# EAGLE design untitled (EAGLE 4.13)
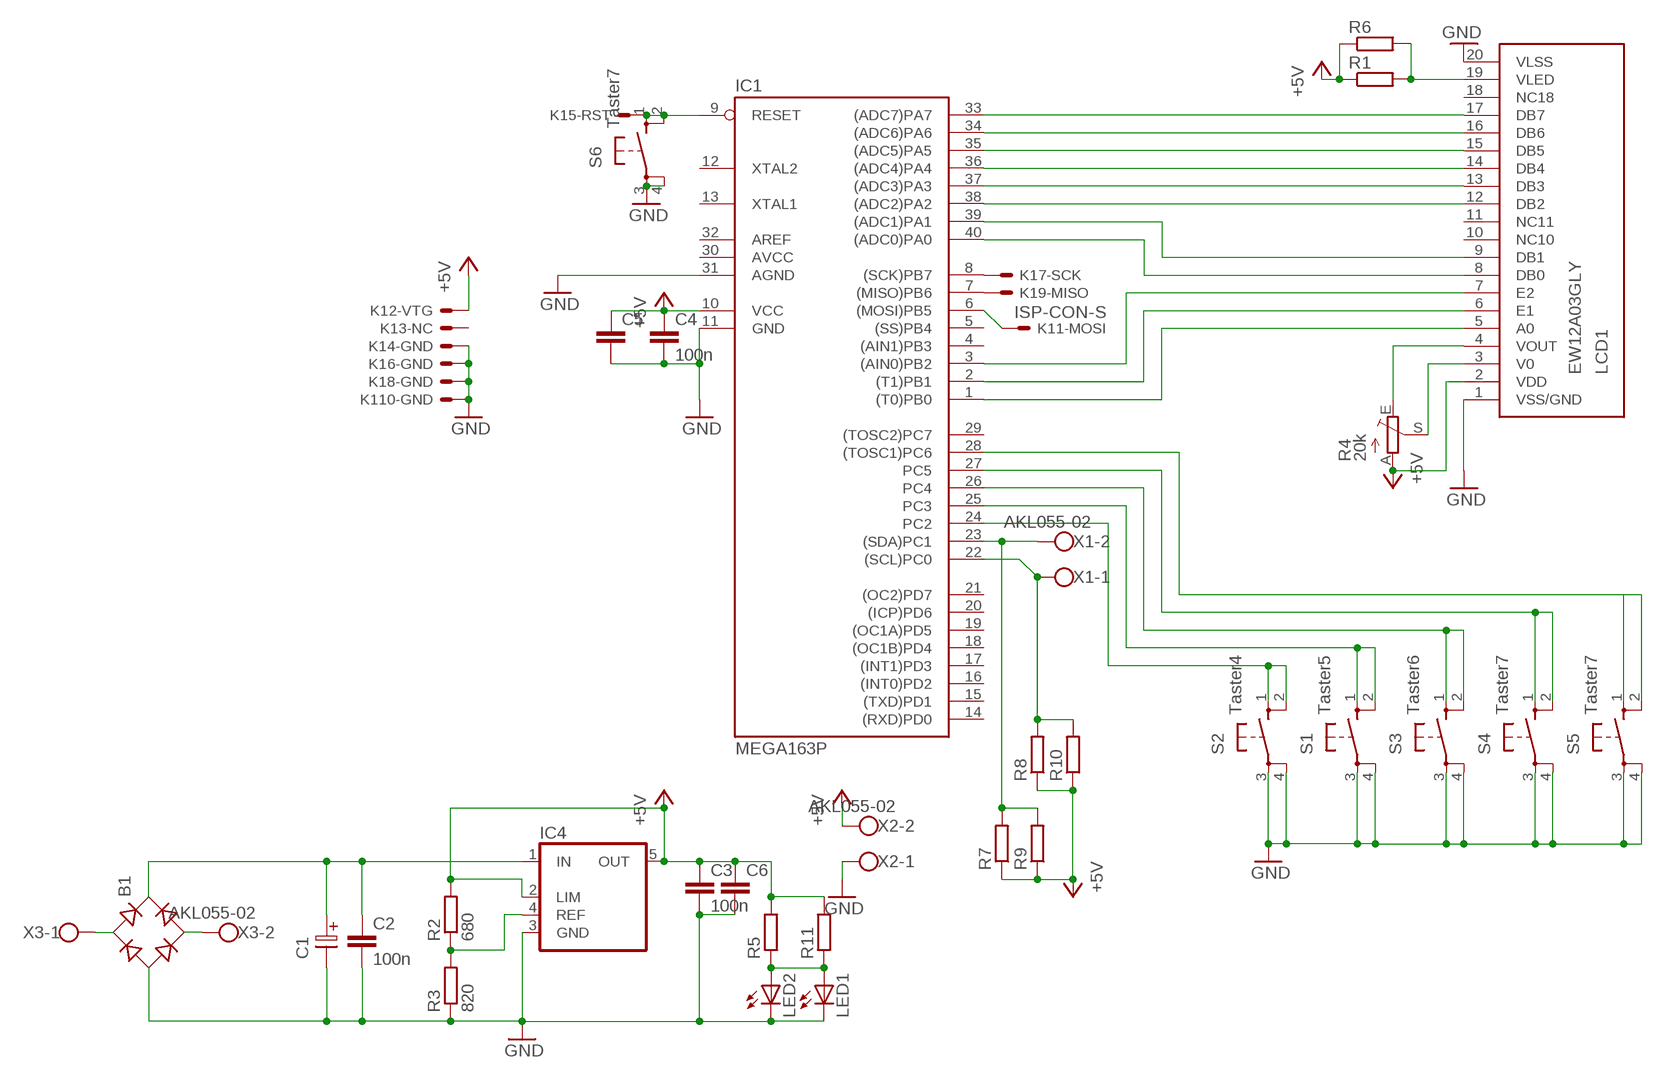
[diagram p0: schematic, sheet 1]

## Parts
B1  RB1A  [RB1A]
C1  _ELC5,0  [ES-5]
C2  100n  C-EU025-025X050  [C025-025X050]
C3  100n  C-EU025-025X050  [C025-025X050]
C4  100n  C-EU025-025X050  [C025-025X050]
C5  C-EUC0805  [C0805]
C6  C-EUC0805  [C0805]
IC1  MEGA163P  [DIL40]
IC4  L200  [L200S]
K1  ISP-CON-S  [ML10]
LCD1  EW12A03GLY  [12A03]
LED1  LED5MM  [LED5MM]
LED2  LEDP-LCC-2-BACK  [P-LCC-2-TOPLED-RG]
R1  R-EU_0204/7  [0204/7]
R2  680  R-EU_0204/2V  [0204V]
R3  820  R-EU_0204/2V  [0204V]
R4  20k  TRIM_EU-S63X  [S63X]
R5  R-EU_M0805  [M0805]
R6  R-EU_R0805  [R0805]
R7  R-EU_0204/7  [0204/7]
R8  R-EU_0204/7  [0204/7]
R9  R-EU_M0805  [M0805]
R10  R-EU_M0805  [M0805]
R11  R-EU_0204/2V  [0204V]
S1  Taster5  10XX  [B3F-10XX]
S2  Taster4  10XX  [B3F-10XX]
S3  Taster6  10XX  [B3F-10XX]
S4  Taster7  10XX  [B3F-10XX]
S5  Taster7  10XX  [B3F-10XX]
S6  Taster7  10XX  [B3F-10XX]
X1  AKL055-02  [AKL055-02]
X2  AKL055-02  [AKL055-02]
X3  AKL055-02  [AKL055-02]

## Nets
+5V: C3.1 C4.1 C5.1 C6.1 IC1.10(VCC) IC4.2(LIM) IC4.5(OUT) K1.2 LCD1.2(VDD) R1.1 R2.2 R4.A R5.2 R6.1 R7.1 R8.1 R9.1 R10.1 R11.2 X2.P$2
GND: B1.- C1.2 C2.2 C3.2 C4.2 C5.2 C6.2 IC1.11(GND) IC1.31(AGND) IC4.3(GND) K1.4 K1.6 K1.8 K1.10 LCD1.1(VSS/GND) LCD1.20(VLSS) LED1.K(C) LED2.C R3.1 S1.3 S1.4 S2.3 S2.4 S3.3 S3.4 S4.3 S4.4 S5.3 S5.4 S6.3 S6.4 X2.P$1
N$1: IC1.40((ADC0)PA0) LCD1.8(DB0)
N$2: IC1.39((ADC1)PA1) LCD1.9(DB1)
N$3: IC1.38((ADC2)PA2) LCD1.12(DB2)
N$4: IC1.37((ADC3)PA3) LCD1.13(DB3)
N$5: IC1.36((ADC4)PA4) LCD1.14(DB4)
N$6: IC1.35((ADC5)PA5) LCD1.15(DB5)
N$7: IC1.34((ADC6)PA6) LCD1.16(DB6)
N$8: IC1.33((ADC7)PA7) LCD1.17(DB7)
N$9: IC1.1((T0)PB0) LCD1.5(A0)
N$10: IC1.2((T1)PB1) LCD1.6(E1)
N$11: IC1.3((AIN0)PB2) LCD1.7(E2)
N$12: LCD1.4(VOUT) R4.E
N$13: LCD1.3(V0) R4.S
N$14: IC1.6((MOSI)PB5) K1.1
N$15: LCD1.19(VLED) R1.2 R6.2
N$16: IC1.9(RESET) K1.5 S6.1 S6.2
N$17: IC1.8((SCK)PB7) K1.7
N$18: IC1.7((MISO)PB6) K1.9
N$19: IC1.22((SCL)PC0) R8.2 R10.2 X1.P$1
N$20: IC1.23((SDA)PC1) R7.2 R9.2 X1.P$2
N$23: B1.AC2 X3.P$2
N$24: B1.AC1 X3.P$1
N$26: LED1.A LED2.A R5.1 R11.1
N$27: IC1.24(PC2) S2.1 S2.2
N$28: IC1.25(PC3) S1.1 S1.2
N$29: IC1.26(PC4) S3.1 S3.2
N$30: IC1.27(PC5) S4.1 S4.2
N$31: IC1.28((TOSC1)PC6) S5.1 S5.2
N$51: B1.+ C1.1 C2.1 IC4.1(IN)
N$54: IC4.4(REF) R2.1 R3.2
Unconnected: IC1.4((AIN1)PB3) IC1.5((SS)PB4) IC1.12(XTAL2) IC1.13(XTAL1) IC1.14((RXD)PD0) IC1.15((TXD)PD1) IC1.16((INT0)PD2) IC1.17((INT1)PD3) IC1.18((OC1B)PD4) IC1.19((OC1A)PD5) IC1.20((ICP)PD6) IC1.21((OC2)PD7) IC1.29((TOSC2)PC7) K1.3 LCD1.10(NC10) LCD1.11(NC11) LCD1.18(NC18)

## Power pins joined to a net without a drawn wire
AREF: IC1.32(AREF)
AVCC: IC1.30(AVCC)

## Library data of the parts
B1 = rectifier:RB1A: RECTIFIER 1 A
C1 = Verschiedenes:_ELC
C2-C6 = rcl:C-EU: CAPACITOR, European symbol
IC1 = atmel:MEGA163*P: MICROCONTROLLER 16 Kbytes FLASH, 1 Kbytes EEPROM 1 Kbytes SRAM UART 8-channel 10 bit ADC hardware multiplier
IC4 = v-reg:L200: VOLTAGE REGULATOR
K1 = I2C:ISP-CON-S
LCD1 = EMERGING:EW12A03GLY
LED1 LED2 = led:LED: LED
R1-R3 R5-R11 = rcl:R-EU_: RESISTOR, European symbol
R4 = pot:TRIM_EU-: POTENTIOMETER
S1-S6 = KEY_B:10XX
X1-X3 = con-riacon:AKL055-02: Anreihbare Anschlussklemme

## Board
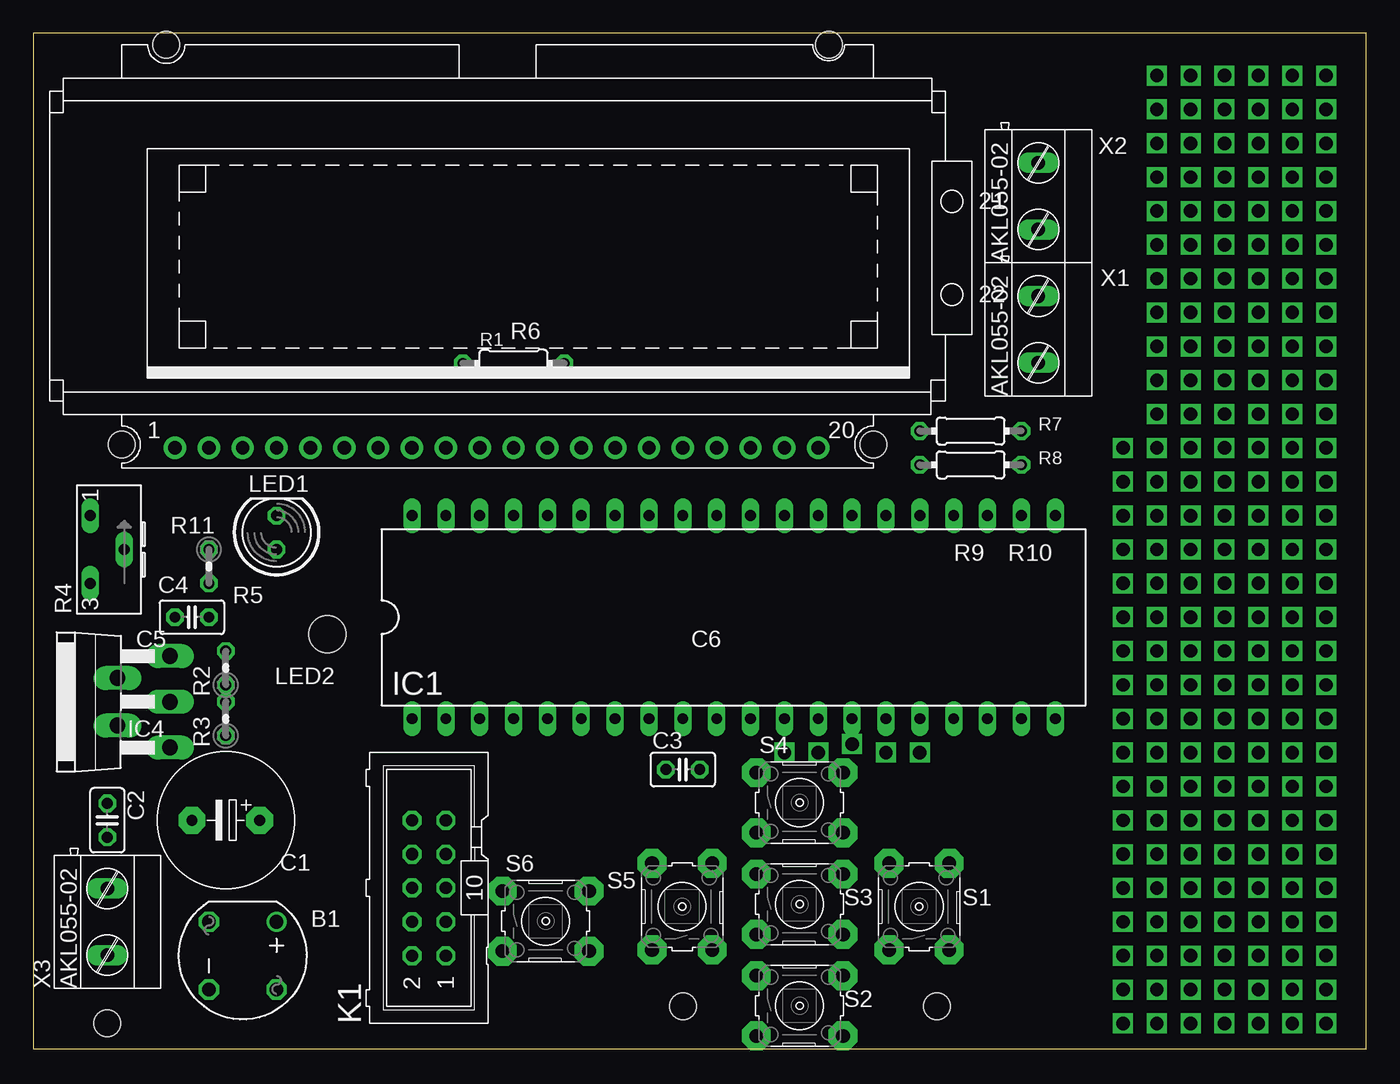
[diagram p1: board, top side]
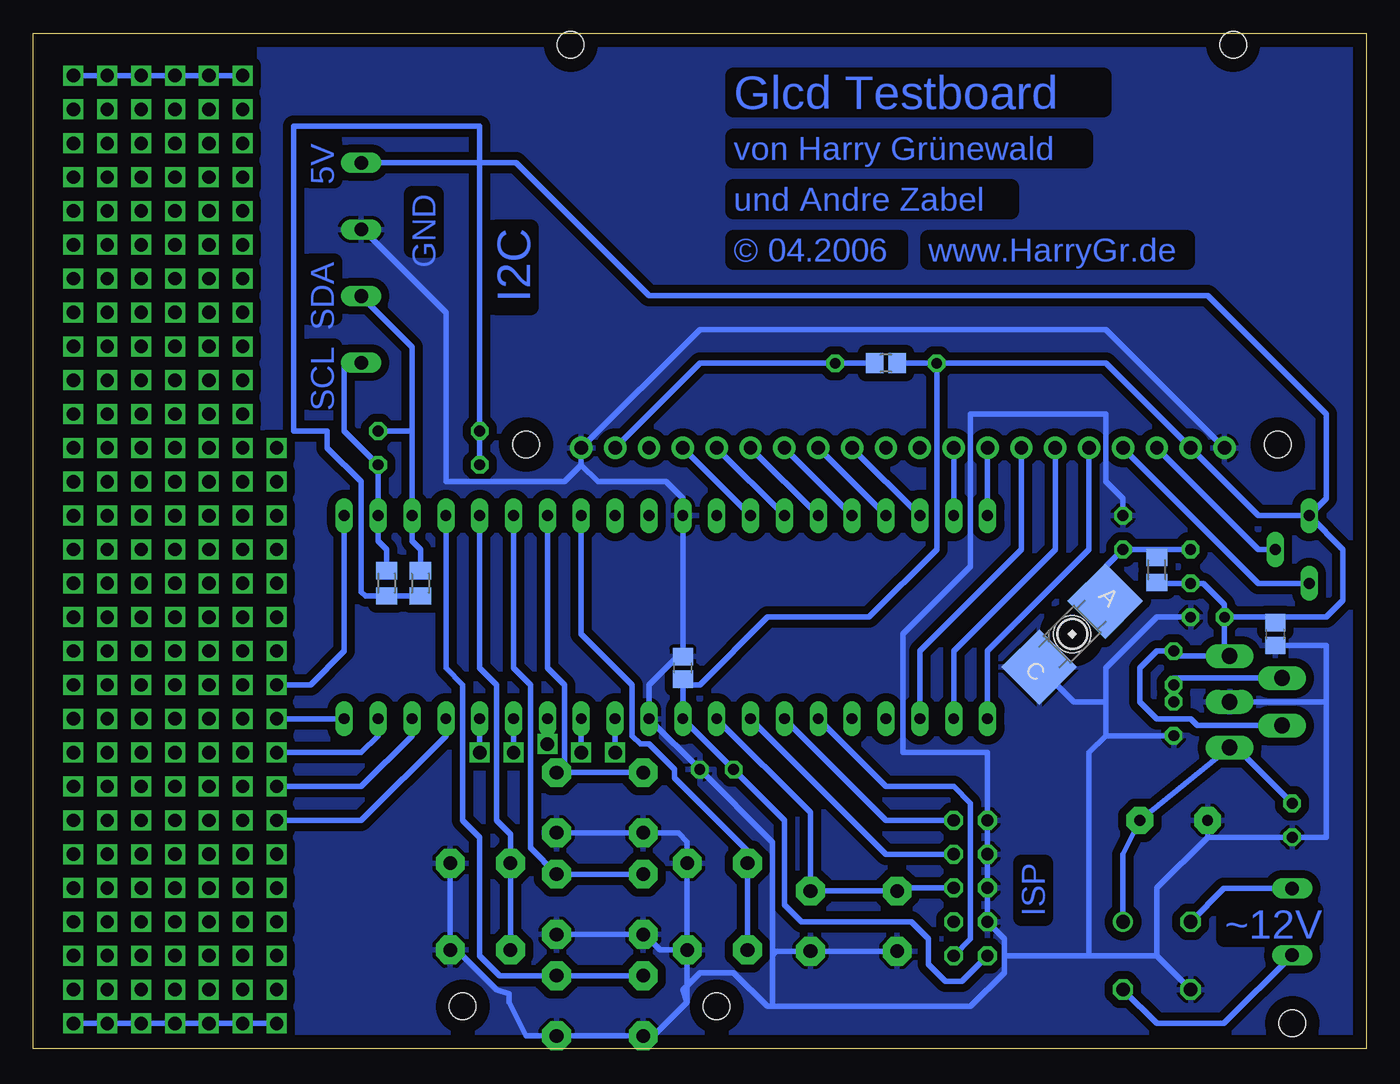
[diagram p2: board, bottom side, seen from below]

Size 100 x 76.19 mm. Coordinates in mm from the lower left corner, seen from the top.
Outline: 0,0 100,0 100,76.19 0,76.19 0,0
Copper layers (1*16): Top 0.035mm / dielectric 1.5mm / Bottom 0.035mm
Design rules "default": minimum track width 10mil, minimum drill 24mil, track to track 8mil, track to pad 8mil, pad to pad 8mil, via to via 8mil, smd to smd 8mil, copper to edge 40mil, drill to drill 8mil, minimum pad ring 10mil, minimum via ring 8mil, stop-mask expansion 4mil, vias tented up to drill 0mil, thermal gap 10mil
Holes 2 mm at 48.73,3.17 67.78,3.17 5.55,1.9

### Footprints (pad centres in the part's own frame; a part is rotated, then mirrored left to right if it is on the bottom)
RB1A = drill 1.016 round: + -2.54,2.54 | drill 1.016 octagon: - 2.54,-2.54; AC1 2.54,2.54; AC2 -2.54,-2.54
ES-5 = drill 0.813 pad 2.007 octagon: 1 -2.54,0; 2 2.54,0
C025-025X050 = drill 0.813 octagon: 1 -1.27,0; 2 1.27,0
C0805 = smd 1.3 x 1.5: 1 -0.85,0; 2 0.85,0
DIL40 = drill 0.813 long: 1 -24.13,-7.62; 2 -21.59,-7.62; 3 -19.05,-7.62; 4 -16.51,-7.62; 5 -13.97,-7.62; 6 -11.43,-7.62; 7 -8.89,-7.62; 8 -6.35,-7.62; 9 -3.81,-7.62; 10 -1.27,-7.62; 11 1.27,-7.62; 12 3.81,-7.62; 13 6.35,-7.62; 14 8.89,-7.62; 15 11.43,-7.62; 16 13.97,-7.62; 17 16.51,-7.62; 18 19.05,-7.62; 19 21.59,-7.62; 20 24.13,-7.62; 21 24.13,7.62; 22 21.59,7.62; 23 19.05,7.62; 24 16.51,7.62; 25 13.97,7.62; 26 11.43,7.62; 27 8.89,7.62; 28 6.35,7.62; 29 3.81,7.62; 30 1.27,7.62; 31 -1.27,7.62; 32 -3.81,7.62; 33 -6.35,7.62; 34 -8.89,7.62; 35 -11.43,7.62; 36 -13.97,7.62; 37 -16.51,7.62; 38 -19.05,7.62; 39 -21.59,7.62; 40 -24.13,7.62
L200S = drill 1.194 long: 1 -3.429,-8.509; 2 -1.778,-4.572; 3 0,-8.509; 4 1.778,-4.572; 5 3.429,-8.509
ML10 = drill 0.914 octagon: 1 -5.08,-1.27; 2 -5.08,1.27; 3 -2.54,-1.27; 4 -2.54,1.27; 5 0,-1.27; 6 0,1.27; 7 2.54,-1.27; 8 2.54,1.27; 9 5.08,-1.27; 10 5.08,1.27
12A03 = drill 1 pad 1.676 round: 1 0,0; 2 2.54,0; 3 5.08,0; 4 7.62,0; 5 10.16,0; 6 12.7,0; 7 15.24,0; 8 17.78,0; 9 20.32,0; 10 22.86,0; 11 25.4,0; 12 27.94,0; 13 30.48,0; 14 33.02,0; 15 35.56,0; 16 38.1,0; 17 40.64,0; 18 43.18,0; 19 45.72,0; 20 48.26,0 | hole 2: -4,0.25; 52.4,0.25; -0.65,30.25; 49.05,30.25
LED5MM = drill 0.813 octagon: A -1.27,0; K 1.27,0
P-LCC-2-TOPLED-RG = smd 4 x 4: A 0,3.5; C 0,-3.5 | hole 2.8: 0,0
0204/7 = drill 0.813 octagon: 1 -3.81,0; 2 3.81,0
0204V = drill 0.813 octagon: 1 -1.27,0; 2 1.27,0
S63X = drill 0.813 long: A 2.54,0; E -2.54,0; S 0,-2.54
M0805 = smd 1.3 x 1.6: 1 -0.95,0; 2 0.95,0
R0805 = smd 1.3 x 1.5: 1 -0.85,0; 2 0.85,0
B3F-10XX = drill 1.016 pad 2.159 octagon: 1 -3.379,2.312; 2 3.123,2.312; 3 -3.379,-2.209; 4 3.123,-2.209
AKL055-02 = drill 1.016 long: P$1 0,-2.5; P$2 0,2.5

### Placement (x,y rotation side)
B1  15.71,6.98 270 top
C1  14.44,17.14 180 top
C2  5.55,17.14 270 top
C3  48.73,20.95 0 top
C4  11.9,32.38 0 top
C5  6.82,31.11 270 bottom
C6  51.27,28.57 90 bottom
IC1  52.54,32.38 0 top
IC4  1.74,26.03 90 top
K1  29.68,12.06 90 top
LCD1  10.63,45.08 0 top
LED1  18.25,38.73 90 top
LED2  22.06,31.11 315 bottom
R1  36.03,51.43 0 top
R2  14.44,28.57 90 top
R3  14.44,24.76 90 top
R4  4.28,37.46 90 top
R5  15.71,35.94 270 bottom
R6  36.03,51.43 180 bottom
R7  70.32,46.35 0 top
R8  70.32,43.81 0 top
R9  70.95,34.92 90 bottom
R10  73.5,34.92 90 bottom
R11  13.17,36.19 270 top
S1  66.51,10.79 90 top
S2  57.62,3.17 0 top
S3  57.62,10.79 0 top
S4  57.62,18.41 0 top
S5  48.73,10.79 90 top
S6  38.57,9.52 0 top
X1  75.4,53.97 0 top
X2  75.4,63.97 0 top
X3  5.55,9.52 0 top

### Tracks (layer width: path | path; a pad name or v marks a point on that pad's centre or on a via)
+5V
  Bottom 0.406: R1.1 19.52,51.43 LCD1.2 8.09,40 R4.A | K1.2 30.31,5.08 31.58,5.08 32.85,6.35 32.85,8.25 34.12,9.52 42.38,9.52 43.65,10.79 43.65,17.14 C3.1 IC1.10 51.27,27.3 | R1.1 32.22,37.46 37.3,32.38 44.92,32.38 50,27.3 51.27,27.3 | R4.A 3.01,41.27 3.01,47.62 11.9,56.51 53.81,56.51 63.77,66.47 66.51,66.47 | C4.1 10.63,29.46 IC4.5 14.44,29.46 R2.2 15.71,29.84 16.98,28.57 16.98,26.03 15.71,24.76 13.17,24.76 12.66,24.25 IC4.2 | C4.1 3.01,32.38 | 3.01,32.38 1.74,33.65 1.74,37.46 R4.A | C4.1 10.63,33.33 12.22,34.92 R11.2 15.71,34.92 R5.2 | R1.1 R6.1 | 3.01,32.38 6.82,32.38 C5.1 | 66.51,66.47 X2.P$2 | 51.27,27.3 C6.1 | R8.1 R7.1 66.51,66.47 | 66.51,66.47 66.51,69.21 80.48,69.21 80.48,46.35 77.94,46.35 77.94,45.08 75.4,42.54 75.4,34.29 75.08,33.97 | 75.08,33.97 R10.1 | R10.1 R9.1 | R10.1 73.5,34.29 73.81,33.97 75.08,33.97
GND
  Bottom 0.406: LCD1.1 19.52,53.97 50,53.97 LCD1.20 | 27.14,6.98 27.14,5.71 29.68,3.17 44.54,3.17 | 27.14,6.98 27.14,8.25 K1.4 K1.6 K1.8 K1.10 28.41,22.22 34.76,22.22 34.76,31.11 29.68,36.19 29.68,47.62 19.52,47.62 19.52,42.54 18.25,41.27 LED1.K | B1.- 15.71,6.98 | 15.71,6.98 15.71,12.06 11.9,15.87 | 11.9,15.87 C1.2 | 11.9,15.87 C2.2 3.01,15.87 3.01,26.03 | 3.01,26.03 IC4.3 | 19.52,23.49 20.79,22.22 20.79,6.98 | 19.52,23.49 R3.1 | 15.71,6.98 20.79,6.98 | C4.2 15.71,32.38 19.52,28.57 19.52,26.03 | 19.52,23.49 19.52,26.03 | 58.89,43.81 57.62,42.54 52.54,42.54 51.27,41.27 IC1.31 51.27,29.84 53.81,27.3 IC1.11 C3.2 44.54,15.49 44.54,6.98 | 20.79,6.98 27.14,6.98 | S4.4 S4.3 54.14,16.2 | S3.4 S3.3 54.14,8.58 52.97,7.41 S5.3 | S5.3 S5.4 50.94,14.27 | 54.14,16.2 51.6,16.2 50.94,15.54 50.94,14.27 | 54.14,16.2 53.81,15.87 | 50.94,14.27 51.27,14.6 | 60.16,0.63 59.83,0.96 S2.3 53.48,0.96 50.94,3.5 | 50.94,3.5 S5.3 | S1.3 68.72,7.31 69.05,6.98 | 68.72,7.92 S1.4 | S2.4 63.03,0.96 64.3,3.5 64.3,4.11 65.24,4.44 68.72,7.92 | S1.3 68.72,6.65 | 68.72,7.92 S1.3 | 44.54,3.17 44.92,3.17 47.46,5.71 50,5.71 51.27,4.44 50.94,3.5 | LCD1.20 59.01,45.08 | 58.89,43.81 LCD1.20 | 58.89,43.81 60.16,42.54 69.05,42.54 69.05,55.24 75.4,61.59 X2.P$1 | 41.69,7.56 41.74,7.62 | 41.69,7.56 S6.4 44.28,7.31 44.54,6.98 | S6.3 41.44,7.31 41.69,7.56 | 44.54,3.17 44.54,6.98 | C5.2 3.01,30.26 3.01,26.03 | LED2.C 21.93,26.03 19.52,26.03
  pour Bottom (isolate 0.61): 0.47,76.83 83.02,76.83 83.02,0.63 0.47,0.63
N$1
  Bottom 0.406: IC1.40 LCD1.8
N$2
  Bottom 0.406: IC1.39 LCD1.9
N$3
  Bottom 0.406: IC1.38 LCD1.12
N$4
  Bottom 0.406: IC1.37 LCD1.13
N$5
  Bottom 0.406: IC1.36 LCD1.14
N$6
  Bottom 0.406: IC1.35 LCD1.15
N$7
  Bottom 0.406: IC1.34 LCD1.16
N$8
  Bottom 0.406: IC1.33 LCD1.17
N$9
  Bottom 0.406: IC1.1 28.41,29.84 20.79,37.46 LCD1.5
N$10
  Bottom 0.406: IC1.2 30.95,29.84 23.33,37.46 LCD1.6
N$11
  Bottom 0.406: IC1.3 33.49,29.84 25.87,37.46 LCD1.7
N$12
  Bottom 0.406: R4.E 8.09,34.92 LCD1.4
N$13
  Bottom 0.406: R4.S 8.09,37.46 LCD1.3
N$14
  Bottom 0.406: K1.1 29.68,8.25 29.68,18.41 30.95,19.68 36.03,19.68 IC1.6
N$15
  Bottom 0.406: LCD1.19 50,51.43 R1.2 R6.2
N$16
  Bottom 0.406: S6.2 41.69,17.72 IC1.9 | S6.2 41.69,11.37 | 34.99,11.83 S6.1 | K1.5 34.76,12.06 34.99,11.83 | 34.99,11.83 S6.2
N$17
  Bottom 0.406: K1.7 36.03,14.6 IC1.8
N$18
  Bottom 0.406: K1.9 36.03,17.14 IC1.7
N$19
  Bottom 0.406: X1.P$1 76.63,51.47 76.67,51.43 76.67,46.35 R8.2 IC1.22 74.13,38.1 73.5,37.46 R10.2
N$20
  Bottom 0.406: X1.P$2 71.59,52.66 71.59,46.35 | 71.59,46.35 IC1.23 71.59,38.1 70.95,37.46 R9.2 | 71.59,46.35 R7.2
N$23
  Bottom 0.406: X3.P$2 10.67,12.02 B1.AC2
N$24
  Bottom 0.406: X3.P$1 10.67,1.9 15.71,1.9 B1.AC1
N$26
  Bottom 0.406: R11.1 15.71,37.46 | 15.71,37.46 R5.1 | 15.71,37.46 LED1.A 19.52,36.19 19.52,33.65 LED2.A
N$27
  Bottom 0.406: IC1.24 69.05,28.57 67.78,27.3 67.78,17.14 66.51,15.87 66.51,6.98 65.01,5.48 S2.2 60.39,5.48 60.16,5.71 arc-90 59.93,5.48 S2.1
N$28
  Bottom 0.406: IC1.25 66.51,28.57 65.24,27.3 65.24,17.14 64.2,16.1 S1.2 64.2,8.48 63.97,8.25 64.2,8.02 S1.1
N$29
  Bottom 0.406: IC1.26 63.97,28.57 62.7,27.3 62.7,15.06 S3.2 54.04,13.1 | S3.1 54.04,13.1 | 54.04,13.1 53.81,13.33
N$30
  Bottom 0.406: IC1.27 61.43,28.57 60.16,27.3 60.16,20.95 | S4.1 59.93,20.72 60.16,20.95 | 60.16,20.95 61.43,20.95 | S4.2 60.39,20.72 60.16,20.95
N$31
  Bottom 0.406: IC1.28 58.89,31.11 55.08,27.3 55.08,23.49 54.45,22.86 53.81,22.86 51.91,20.95 51.91,20.32 46.42,14.83 S5.2 46.42,7.21 | S5.1 46.42,7.21 | 46.42,7.21 46.19,6.98
N$32  (via drill 1)
  Bottom 0.406: 76.67,24.76 v81.75,24.76
N$33  (via drill 1)
  other vias: 84.29,24.76
N$34  (via drill 1)
  Bottom 0.406: v81.75,19.68 75.4,19.68 71.59,23.49
N$35  (via drill 1)
  Bottom 0.406: v81.75,17.14 75.4,17.14 69.05,23.49
N$36  (via drill 1)
  other vias: 81.75,14.6
N$37  (via drill 1)
  other vias: 81.75,12.06
N$38  (via drill 1)
  other vias: 81.75,9.52
N$39  (via drill 1)
  other vias: 81.75,6.98
N$40  (via drill 1)
  other vias: 81.75,4.44
N$42  (via drill 1)
  other vias: 84.29,19.68
N$43  (via drill 1)
  other vias: 84.29,17.14
N$44  (via drill 1)
  other vias: 81.75,29.84
N$45  (via drill 1)
  other vias: 81.75,32.38
N$46  (via drill 1)
  other vias: 81.75,34.92
N$47  (via drill 1)
  other vias: 81.75,37.46
N$48  (via drill 1)
  other vias: 81.75,40
N$49  (via drill 1)
  other vias: 81.75,42.54
N$50  (via drill 1)
  other vias: 81.75,45.08
N$51
  Bottom 0.406: B1.+ 18.25,14.6 C1.1 IC4.1 9.74,22.6 C2.1
N$52  (via drill 1)
  Bottom 0.406: 76.67,38.73 76.67,29.84 79.21,27.3 v81.75,27.3
N$53  (via drill 1)
  Bottom 0.406: 74.13,23.49 75.4,22.22 v81.75,22.22
N$54
  Bottom 0.406: IC4.4 14.44,27.81 R2.1 R3.2
N$55  (via drill 1)
  Bottom 0.406: v66.51,22.22 66.51,23.49
N$56  (via drill 1)
  Bottom 0.406: v63.97,22.22 63.97,23.49
N$57  (via drill 1)
  Bottom 0.406: v58.89,22.22 58.89,23.49
N$58  (via drill 1)
  Bottom 0.406: v56.35,22.22 56.35,23.49
N$59  (via drill 1)
  other vias: 61.43,22.86
N$60  (via drill 1)
  other vias: 84.29,14.6
N$61  (via drill 1)
  other vias: 84.29,12.06
N$62  (via drill 1)
  other vias: 84.29,9.52
N$63  (via drill 1)
  other vias: 84.29,6.98
N$64  (via drill 1)
  other vias: 84.29,4.44
N$66  (via drill 1)
  other vias: 84.29,29.84
N$67  (via drill 1)
  other vias: 84.29,32.38
N$68  (via drill 1)
  other vias: 84.29,34.92
N$69  (via drill 1)
  other vias: 84.29,37.46
N$70  (via drill 1)
  other vias: 84.29,40
N$71  (via drill 1)
  other vias: 84.29,42.54
N$72  (via drill 1)
  other vias: 84.29,45.08
N$73  (via drill 1)
  other vias: 84.29,27.3
N$74  (via drill 1)
  other vias: 84.29,22.22
N$75  (via drill 1)
  other vias: 84.29,52.7
N$76  (via drill 1)
  other vias: 84.29,47.62
N$77  (via drill 1)
  other vias: 86.83,24.76
N$78  (via drill 1)
  other vias: 86.83,19.68
N$79  (via drill 1)
  other vias: 86.83,17.14
N$80  (via drill 1)
  other vias: 86.83,14.6
N$81  (via drill 1)
  other vias: 86.83,12.06
N$82  (via drill 1)
  other vias: 86.83,9.52
N$83  (via drill 1)
  other vias: 86.83,6.98
N$84  (via drill 1)
  other vias: 84.29,57.78
N$85  (via drill 1)
  other vias: 84.29,60.32
N$86  (via drill 1)
  other vias: 84.29,62.86
N$87  (via drill 1)
  other vias: 84.29,65.4
N$88  (via drill 1)
  other vias: 84.29,67.94
N$89  (via drill 1)
  other vias: 84.29,70.48
N$91  (via drill 1)
  other vias: 84.29,55.24
N$92  (via drill 1)
  other vias: 84.29,50.16
N$93  (via drill 1)
  other vias: 86.83,4.44
N$95  (via drill 1)
  other vias: 86.83,29.84
N$96  (via drill 1)
  other vias: 86.83,32.38
N$97  (via drill 1)
  other vias: 86.83,34.92
N$98  (via drill 1)
  other vias: 86.83,37.46
N$99  (via drill 1)
  other vias: 86.83,40
N$100  (via drill 1)
  other vias: 86.83,42.54
N$101  (via drill 1)
  other vias: 86.83,45.08
N$102  (via drill 1)
  other vias: 86.83,27.3
N$103  (via drill 1)
  other vias: 86.83,22.22
N$104  (via drill 1)
  other vias: 86.83,52.7
N$105  (via drill 1)
  other vias: 86.83,47.62
N$106  (via drill 1)
  other vias: 86.83,57.78
N$107  (via drill 1)
  other vias: 86.83,60.32
N$108  (via drill 1)
  other vias: 86.83,62.86
N$109  (via drill 1)
  other vias: 86.83,65.4
N$110  (via drill 1)
  other vias: 86.83,67.94
N$111  (via drill 1)
  other vias: 86.83,70.48
N$113  (via drill 1)
  other vias: 86.83,55.24
N$114  (via drill 1)
  other vias: 86.83,50.16
N$115  (via drill 1)
  other vias: 89.37,24.76
N$116  (via drill 1)
  other vias: 89.37,19.68
N$117  (via drill 1)
  other vias: 89.37,17.14
N$118  (via drill 1)
  other vias: 89.37,14.6
N$119  (via drill 1)
  other vias: 89.37,12.06
N$120  (via drill 1)
  other vias: 89.37,9.52
N$121  (via drill 1)
  other vias: 89.37,6.98
N$122  (via drill 1)
  other vias: 89.37,4.44
N$124  (via drill 1)
  other vias: 89.37,29.84
N$125  (via drill 1)
  other vias: 89.37,32.38
N$126  (via drill 1)
  other vias: 89.37,34.92
N$127  (via drill 1)
  other vias: 89.37,37.46
N$128  (via drill 1)
  other vias: 89.37,40
N$129  (via drill 1)
  other vias: 89.37,42.54
N$130  (via drill 1)
  other vias: 89.37,45.08
N$131  (via drill 1)
  other vias: 89.37,27.3
N$132  (via drill 1)
  other vias: 89.37,22.22
N$133  (via drill 1)
  other vias: 89.37,52.7
N$134  (via drill 1)
  other vias: 89.37,47.62
N$135  (via drill 1)
  other vias: 89.37,57.78
N$136  (via drill 1)
  other vias: 89.37,60.32
N$137  (via drill 1)
  other vias: 89.37,62.86
N$138  (via drill 1)
  other vias: 89.37,65.4
N$139  (via drill 1)
  other vias: 89.37,67.94
N$140  (via drill 1)
  other vias: 89.37,70.48
N$142  (via drill 1)
  other vias: 89.37,55.24
N$143  (via drill 1)
  other vias: 89.37,50.16
N$144  (via drill 1)
  other vias: 91.91,24.76
N$145  (via drill 1)
  other vias: 91.91,19.68
N$146  (via drill 1)
  other vias: 91.91,17.14
N$147  (via drill 1)
  other vias: 91.91,14.6
N$148  (via drill 1)
  other vias: 91.91,12.06
N$149  (via drill 1)
  other vias: 91.91,9.52
N$150  (via drill 1)
  other vias: 91.91,6.98
N$151  (via drill 1)
  other vias: 91.91,4.44
N$153  (via drill 1)
  other vias: 91.91,29.84
N$154  (via drill 1)
  other vias: 91.91,32.38
N$155  (via drill 1)
  other vias: 91.91,34.92
N$156  (via drill 1)
  other vias: 91.91,37.46
N$157  (via drill 1)
  other vias: 91.91,40
N$158  (via drill 1)
  other vias: 91.91,42.54
N$159  (via drill 1)
  other vias: 91.91,45.08
N$160  (via drill 1)
  other vias: 91.91,27.3
N$161  (via drill 1)
  other vias: 91.91,22.22
N$162  (via drill 1)
  other vias: 91.91,52.7
N$163  (via drill 1)
  other vias: 91.91,47.62
N$164  (via drill 1)
  other vias: 91.91,57.78
N$165  (via drill 1)
  other vias: 91.91,60.32
N$166  (via drill 1)
  other vias: 91.91,62.86
N$167  (via drill 1)
  other vias: 91.91,65.4
N$168  (via drill 1)
  other vias: 91.91,67.94
N$169  (via drill 1)
  other vias: 91.91,70.48
N$171  (via drill 1)
  other vias: 91.91,55.24
N$172  (via drill 1)
  other vias: 91.91,50.16
N$173  (via drill 1)
  other vias: 94.45,24.76
N$174  (via drill 1)
  other vias: 94.45,19.68
N$175  (via drill 1)
  other vias: 94.45,17.14
N$176  (via drill 1)
  other vias: 94.45,14.6
N$177  (via drill 1)
  other vias: 94.45,12.06
N$178  (via drill 1)
  other vias: 94.45,9.52
N$179  (via drill 1)
  other vias: 94.45,6.98
N$180  (via drill 1)
  other vias: 94.45,4.44
N$182  (via drill 1)
  other vias: 94.45,29.84
N$183  (via drill 1)
  other vias: 94.45,32.38
N$184  (via drill 1)
  other vias: 94.45,34.92
N$185  (via drill 1)
  other vias: 94.45,37.46
N$186  (via drill 1)
  other vias: 94.45,40
N$187  (via drill 1)
  other vias: 94.45,42.54
N$188  (via drill 1)
  other vias: 94.45,45.08
N$189  (via drill 1)
  other vias: 94.45,27.3
N$190  (via drill 1)
  other vias: 94.45,22.22
N$191  (via drill 1)
  other vias: 94.45,52.7
N$192  (via drill 1)
  other vias: 94.45,47.62
N$193  (via drill 1)
  other vias: 94.45,57.78
N$194  (via drill 1)
  other vias: 94.45,60.32
N$195  (via drill 1)
  other vias: 94.45,62.86
N$196  (via drill 1)
  other vias: 94.45,65.4
N$197  (via drill 1)
  other vias: 94.45,67.94
N$198  (via drill 1)
  other vias: 94.45,70.48
N$200  (via drill 1)
  other vias: 94.45,55.24
N$201  (via drill 1)
  other vias: 94.45,50.16
N$202  (via drill 1)
  other vias: 96.99,24.76
N$203  (via drill 1)
  other vias: 96.99,19.68
N$204  (via drill 1)
  other vias: 96.99,17.14
N$205  (via drill 1)
  other vias: 96.99,14.6
N$206  (via drill 1)
  other vias: 96.99,12.06
N$207  (via drill 1)
  other vias: 96.99,9.52
N$208  (via drill 1)
  other vias: 96.99,6.98
N$209  (via drill 1)
  other vias: 96.99,4.44
N$210  (via drill 1)
  Bottom 0.406: v96.99,1.9 v94.45,1.9 v91.91,1.9 v89.37,1.9 v86.83,1.9 v84.29,1.9 v81.75,1.9
N$211  (via drill 1)
  other vias: 96.99,29.84
N$212  (via drill 1)
  other vias: 96.99,32.38
N$213  (via drill 1)
  other vias: 96.99,34.92
N$214  (via drill 1)
  other vias: 96.99,37.46
N$215  (via drill 1)
  other vias: 96.99,40
N$216  (via drill 1)
  other vias: 96.99,42.54
N$217  (via drill 1)
  other vias: 96.99,45.08
N$218  (via drill 1)
  other vias: 96.99,27.3
N$219  (via drill 1)
  other vias: 96.99,22.22
N$220  (via drill 1)
  other vias: 96.99,52.7
N$221  (via drill 1)
  other vias: 96.99,47.62
N$222  (via drill 1)
  other vias: 96.99,57.78
N$223  (via drill 1)
  other vias: 96.99,60.32
N$224  (via drill 1)
  other vias: 96.99,62.86
N$225  (via drill 1)
  other vias: 96.99,65.4
N$226  (via drill 1)
  other vias: 96.99,67.94
N$227  (via drill 1)
  other vias: 96.99,70.48
N$228  (via drill 1)
  Bottom 0.406: v96.99,73.02 v94.45,73.02 v91.91,73.02 v89.37,73.02 v86.83,73.02 v84.29,73.02
N$229  (via drill 1)
  other vias: 96.99,55.24
N$230  (via drill 1)
  other vias: 96.99,50.16

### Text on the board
Bottom: Glcd Testboard | 5V | von Harry Grünewald | GND | und Andre Zabel | I2C | www.HarryGr.de | © 04.2006 | SDA | SCL | ISP | ~12V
